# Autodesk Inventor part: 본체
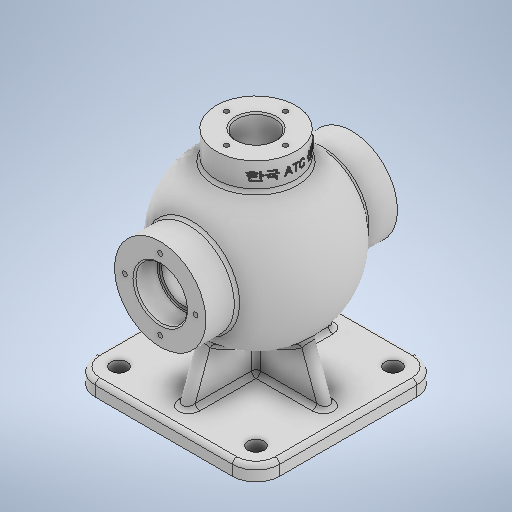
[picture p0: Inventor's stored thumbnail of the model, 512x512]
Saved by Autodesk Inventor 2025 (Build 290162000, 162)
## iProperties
Created: 2024-07
Part Number: 본체
Material: 일반
Document SubType Name: Modeling
Designer: deana
Density: 1 g/cm^3
Appearance: 기본값
Author: deana
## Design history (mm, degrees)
sketch "스케치1"
  geometry: L1 (46.5, -62.5)-(-46.5, -62.5); L2 (-62.5, -46.5)-(-62.5, 46.5); L3 (-46.5, 62.5)-(46.5, 62.5); L4 (62.5, 46.5)-(62.5, -46.5); L5 (62.5, -62.5)-(-62.5, 62.5); L6 (-62.5, -62.5)-(62.5, 62.5); C1 r 5.5 at (46.5, -46.5); C2 r 5.5 at (-46.5, -46.5); C3 r 5.5 at (46.5, 46.5); C4 r 5.5 at (-46.5, 46.5); A1 r 16 centre (46.5, -46.5) between (46.5, -62.5) and (62.5, -46.5); A2 r 16 centre (-46.5, -46.5) between (-62.5, -46.5) and (-46.5, -62.5); A3 r 16 centre (-46.5, 46.5) between (-46.5, 62.5) and (-62.5, 46.5); A4 r 16 centre (46.5, 46.5) between (62.5, 46.5) and (46.5, 62.5); 1 further point
  constraints: 12 end point, 8 centre point, 8 point on circle, 8 point on line, 8 tangent, 4 coincident, 3 equal radius, 2 midpoint, 2 parallel, 1 horizontal, 1 perpendicular
  dimensions: "d0" = 125 distance of L5.end L6.end; "d1" = 125 distance of L6.start L5.end; "d2" = 16 radius of A1; "d3" = 11 diameter of C1; "d4" = 11 diameter of C2; "d5" = 11 diameter of C3; "d6" = 11 diameter of C4
extrude "돌출1" new body sketch "스케치1" distance "d7" = 10; taper "d8" = 0 deg
sketch "스케치2"
  geometry: L1 (0, 46.5)-(0, -46.5) reference; L2 (139, 0)-(31, 0); L3 (139, 0)-(31, 0); A1 r 54 centre (85, 0) between (31, 0) and (139, 0); A2 r 54 centre (85, 0) between (139, 0) and (31, 0); 4 further points
  constraints: 5 point on circle, 4 end point, 3 midpoint, 2 centre point, 1 coincident, 1 collinear, 1 horizontal, 1 horizontal alignment
  dimensions: "d10" = 108 diameter of A1; "d11" = 85 distance of point (0, 0) A1.centre
revolve "회전1" sketch "스케치2" stored, may be unused: angle "d12" = 90 deg
sketch "스케치3"
  geometry: C1 r 31 at (0, 85); 1 further point
  constraints: 1 centre point, 1 vertical alignment
  dimensions: "d13" = 62 diameter of C1; "d14" = 85 distance of point (0, 0) C1.centre
extrude "돌출2" join sketch "스케치3" stored distance "d15" = 130; taper "d16" = 0 deg
node "작업 평면1"
sketch "스케치7"
  geometry: C1 r 27 at (0, 0); C2 r 13 at (0, 0); 1 further point
  constraints: 2 centre point, 2 coincident
  dimensions: "d43" = 54 diameter of C1; "d44" = 26 diameter of C2
extrude "돌출3" join sketch "스케치7" distance "d45" = 65; taper "d46" = 0 deg
sketch "스케치4"
  geometry: C1 r 31 at (0, 0) reference; 2 further points
  constraints: 1 coincident
hole "구멍1" sketch "스케치4" at (0, 0) diameter "d17" = 30; stored, may be unused: countersink angle "d21" = 90 deg, drill point angle "d23" = 0 deg; dims "d18" = 6, "d19" = 4, "d20" = 2, "d22" = 30
sketch "스케치5"
  geometry: C1 r 31 at (0, 0) reference; 2 further points
  constraints: 1 coincident
hole "구멍2" sketch "스케치5" at (0, 0) diameter "d24" = 35; stored, may be unused: countersink angle "d28" = 90 deg, drill point angle "d30" = 0 deg; dims "d25" = 6, "d26" = 4, "d27" = 2, "d29" = 16
sketch "스케치6"
  geometry: C1 r 31 at (0, 0) reference; 2 further points
  constraints: 1 coincident
hole "구멍3" sketch "스케치6" at (0, 0) diameter "d31" = 35; stored, may be unused: countersink angle "d35" = 90 deg, drill point angle "d37" = 0 deg; dims "d32" = 6, "d33" = 4, "d34" = 2, "d36" = 16
fillet "모깎기2" dims "d38" = 0.6
chamfer "모따기1" distance "d39" = 1; stored, may be unused: second distance "d40" = 2, angle "d41" = 45 deg
extrude "돌출4" cut sketch "스케치7" distance "d47" = 65; taper "d48" = 0 deg
fillet "모깎기3" dims "d49" = 3
chamfer "모따기2" distance "d50" = 1; stored, may be unused: second distance "d51" = 2, angle "d52" = 45 deg
sketch "스케치8"
  geometry: L1 (57.519, 33.204)-(10, 50.5); L2 (10, 50.5)-(10, -50.5); L3 (10, -50.5)-(57.519, -33.204); L4 (57.519, -33.204)-(57.519, 33.204); L5 (10, 0)-(89.28, 0); L6 (0, -62.5)-(10, -62.5) reference; L7 (10, 46.5)-(10, -46.5) reference; 1 further point
  constraints: 10 end point, 1 collinear, 1 horizontal alignment, 1 midpoint, 1 parallel, 1 perpendicular, 1 vertical, 1 other
  dimensions: "d53" = 12 distance of L6.end L2.end; "d55" = 20 deg angle of L6 L3; "d56" = 47.51942 distance between parallel lines of L2 L4
extrude "돌출5" join sketch "스케치8" stored distance "d57" = 8; taper "d58" = 0 deg
sketch "스케치12"
  geometry: L1 (-32.966, 58.173)-(-50.5, 10); L2 (-50.5, 10)-(50.5, 10); L3 (50.5, 10)-(32.966, 58.173); L4 (32.966, 58.173)-(-32.966, 58.173); L5 (46.5, 0)-(-46.5, 0) reference; L6 (0, 0)-(0, 70); L7 (46.5, 10)-(-46.5, 10) reference; L8 (62.5, 0)-(62.5, 10) reference; 1 further point
  constraints: 10 end point, 1 collinear, 1 horizontal, 1 parallel, 1 vertical, 1 vertical alignment, 2 other
  dimensions: "d63" = 12 distance of L8.end L2.end; "d64" = 20 deg angle of L8 L3; "d65" = 48.1733 distance between parallel lines of L2 L4
extrude "돌출6" join sketch "스케치12" stored distance "d66" = 8; taper "d67" = 0 deg
feature "전체 둥근 모깎기1"
feature "전체 둥근 모깎기2"
feature "전체 둥근 모깎기3"
feature "전체 둥근 모깎기4"
fillet "모깎기4" dims "d68" = 3
fillet "모깎기5" dims "d69" = 3
node "작업 평면2"
sketch "스케치13"
  geometry: L1 (150, -27)-(150, 27) reference; 2 further points
  constraints: 1 horizontal alignment, 1 other
  dimensions: "d71" = 9 distance from line of L1 point (141, 0)
feature "엠보싱1" sketch "스케치13" dims "d72" = 0.5, "d73" = 0
fillet "모깎기6" dims "d74" = 3
fillet "모깎기7" dims "d75" = 3
fillet "모깎기8" dims "d76" = 3
sketch "스케치14" dims "d84" = 48
  geometry: C1 r 31 at (0, 0) reference; C2 r 15 at (0, 0) reference; 3 further points
  constraints: 2 vertical alignment, 1 coincident, 2 other
hole "구멍4" sketch "스케치14" at (0, 24) diameter "d77" = 3.242; stored, may be unused: countersink angle "d81" = 90 deg, drill point angle "d83" = 120 deg; dims "d78" = 12, "d79" = 4, "d80" = 2, "d82" = 15
sketch "스케치15" dims "d95" = 40
  geometry: 3 further points
  constraints: 2 horizontal alignment, 1 coincident, 2 other
hole "구멍5" sketch "스케치15" at (-20, 0) diameter "d88" = 3.242; stored, may be unused: countersink angle "d92" = 90 deg, drill point angle "d94" = 120 deg; dims "d89" = 9, "d90" = 4, "d91" = 2, "d93" = 11
sketch "스케치16"
  geometry: L1 (129, 0)-(41, 0); A1 r 44 centre (85, 0) between (129, 0) and (41, 0); A2 r 44 centre (85, 0) between (41, 0) and (129, 0); 1 further point
  constraints: 4 point on circle, 2 centre point, 2 end point, 1 horizontal, 1 horizontal alignment, 1 midpoint
  dimensions: "d99" = 88 diameter of A1; "d100" = 85 distance of point (0, 0) A1.centre
revolve "회전2" sketch "스케치16" stored, may be unused: angle "d101" = 90 deg
node "솔리드1"
pattern_circular "원형 패턴1" dims angle "d86" = 360 deg
mirror "미러1"
pattern_circular "원형 패턴2" dims angle "d97" = 360 deg
feature "A9D066F2-1C7D-4E18-AEED-F7BC21143FA4" dims "d17" = 30, "d18" = 6, "d19" = 4, "d20" = 2, "d21" = 90 deg, "d22" = 30, "d23" = 0
other parameters: "d42" = 85
